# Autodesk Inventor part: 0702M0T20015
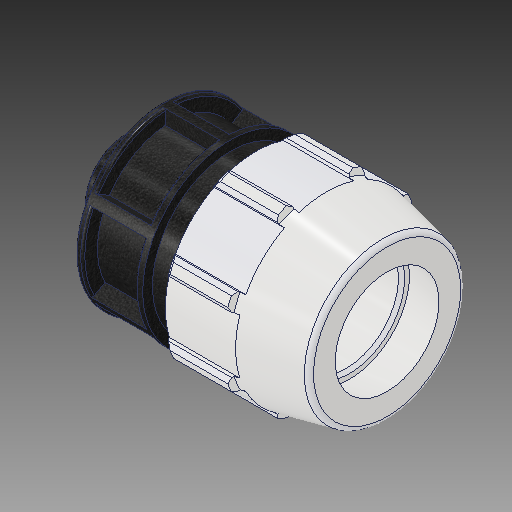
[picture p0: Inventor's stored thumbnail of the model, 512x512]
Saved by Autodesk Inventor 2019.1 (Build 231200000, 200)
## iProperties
Created: 2017-02
Part Number: 0702M0T20015
Material: PVC-Piping
Description: PLASSON MALE ADAPTOR 2'' - 1 1/2''M
Document SubType Name: Modeling
Designer: KIM
Mass: 92.6774 g
Surface Area: 199.44 cm^2
Volume: 66.1981 cm^3
Density: 1.4 g/cm^3
Appearance: PTFE
Author: KIM
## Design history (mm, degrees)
derived "0702M0T.ipt"
feature "Solid1::0702M0T.ipt"
tag "TaggingFeature1"
body "Solid1"
other parameters: "d2" = 60.1, "d4" = 21.69886, "d5" = 37.973, "d7" = 113.03, "d8" = 84.7725, "d9" = 21.69886, "d11" = 4.33977, "d12" = 90.424, "d13" = 120 deg, "d14" = 90.15, "d15" = 12 deg, "d16" = 101.727, "d18" = 3.005, "d19" = 35 deg, "d20" = 17.5 deg, "d21" = 105.1179, "d23" = 0, "d25" = 360 deg, "d27" = 2.2606, "d34" = 5.6515, "d36" = 0, "d42" = 37.973, "d43" = 3.3909, "d46" = 1.803, "d51" = 151.892, "d52" = 22.098, "d53" = 1.202, "d55" = 360 deg, "d57" = 47.803, "d58" = 33.4621, "d59" = 30.3784, "d61" = 27.178, "d_" = 60.1, "E_" = 113.03, "H_" = 151.892, "l_" = 123.952, "l_2" = 22.098, "G_" = 47.803
